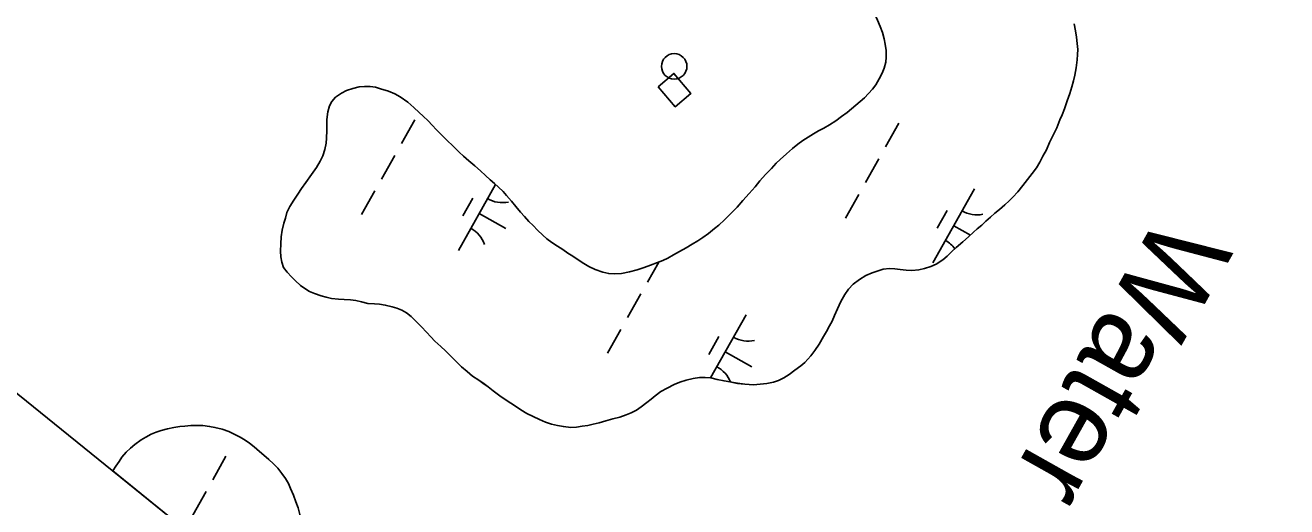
# Model space of a CAD drawing. Extents: x 3913936 to 3933962, y 195330 to 217741.
# Drawn here: x 3922581 to 3923324, y 198286 to 198569 of the extents above; entities that cross this region are included whole.
import ezdxf

# ---------------------------------------------------------------- set-up
doc = ezdxf.new("R2010")
doc.units = 0
for name, color, linetype in [('V-CHAN-DOCK', 7, 'Continuous'), ('V-DOMW-TANK', 7, 'Continuous'), ('V-GRID-FRAM', 7, 'Continuous'), ('V-RIVR-IDEN', 7, 'Continuous'), ('V-TOPO-SHOR', 7, 'Continuous'), ('V-WETL-SWMP', 7, 'Continuous')]:
    doc.layers.add(name, color=color, linetype=linetype)

msp = doc.modelspace()

# ---------------------------------------------------------------- linework, layer by layer
at = {"layer": 'V-CHAN-DOCK'}
msp.add_lwpolyline([(3922953.66, 198532.77), (3922963.71, 198521.05), (3922972.88, 198528.91), (3922962.83, 198540.63)], close=True, dxfattribs=at)
at = {"layer": 'V-DOMW-TANK'}
msp.add_circle((3922963.05, 198544.81), 7.5, dxfattribs=at)
at = {"layer": 'V-GRID-FRAM'}
msp.add_lwpolyline([(3932010.33, 210314.99), (3924440.13, 196848.23), (3917917.56, 202110.57), (3924798.65, 214359.02), (3932010.33, 210314.99)], dxfattribs=at)
at = {"layer": 'V-TOPO-SHOR'}
for points in [[(3923087.39, 198557.97), (3923086.66, 198560.96), (3923085.72, 198564.68), (3923084.47, 198568.29), (3923082.91, 198571.9), (3923081.25, 198575.62), (3923079.69, 198579.23), (3923078.65, 198582.12), (3923072.01, 198591.33)], [(3923198.71, 198569.75), (3923199.45, 198565.72), (3923200.08, 198562), (3923200.5, 198558.29), (3923200.82, 198554.77), (3923200.62, 198551.78), (3923200.53, 198548.58), (3923199.81, 198543.93), (3923199, 198539.58), (3923198.29, 198536.28), (3923197.37, 198532.76), (3923196.04, 198528.83), (3923194.6, 198524.49), (3923192.96, 198519.84), (3923191.52, 198516.22), (3923190.29, 198513.33), (3923188.45, 198508.57), (3923186.4, 198504.33), (3923184.24, 198499.98), (3923182.29, 198495.74), (3923180.23, 198491.91), (3923178.48, 198488.4), (3923176.53, 198485.09), (3923173.96, 198481.67), (3923171.28, 198478.15), (3923168.4, 198474.63), (3923165.42, 198471.01), (3923162.64, 198467.9), (3923160.37, 198465.62), (3923157.9, 198463.24), (3923154.7, 198460.54), (3923152.02, 198458.37), (3923149.34, 198456.09), (3923146.66, 198453.7), (3923144.19, 198451.42), (3923141.62, 198449.15), (3923139.35, 198447.18), (3923136.36, 198444.48), (3923133.06, 198441.58), (3923129.25, 198438.26), (3923126.47, 198435.57), (3923123.79, 198433.08), (3923121.21, 198431.01), (3923117.4, 198428.42), (3923114.2, 198427.07), (3923110.49, 198425.82), (3923107.18, 198425.08), (3923102.95, 198424.66), (3923099.64, 198424.86), (3923096.13, 198425.26), (3923093.03, 198425.66), (3923089.93, 198425.76), (3923086.11, 198425.44), (3923083.22, 198424.5), (3923079.61, 198423.25), (3923076, 198421.69), (3923072.28, 198419.41), (3923068.57, 198416.61), (3923065.79, 198413.71), (3923063.53, 198410.5), (3923061.16, 198406.36), (3923059.32, 198402.02), (3923057.57, 198398.09), (3923056.14, 198394.78), (3923054.59, 198392.19), (3923052.74, 198388.68), (3923051, 198385.78), (3923048.43, 198381.33), (3923045.85, 198377.6), (3923043.48, 198374.4), (3923039.98, 198370.56), (3923037.72, 198368.6), (3923034.21, 198366), (3923030.81, 198363.41), (3923027.72, 198361.44), (3923024.52, 198359.99), (3923021.53, 198359.05), (3923017.6, 198358.21), (3923013.68, 198357.79), (3923009.86, 198357.46), (3923004.59, 198357.76), (3923000.25, 198358.27), (3922995.81, 198359.08), (3922992.4, 198359.69), (3922988.26, 198360.61), (3922984.54, 198361.42), (3922981.23, 198361.72), (3922978.03, 198361.71), (3922974.31, 198361.19), (3922970.19, 198360.14), (3922966.37, 198358.89), (3922963.07, 198357.54), (3922958.84, 198355.46), (3922955.23, 198353.39), (3922951.83, 198350.9), (3922949.46, 198349.03), (3922946.98, 198347.06), (3922943.68, 198344.37)], [(3922790.08, 198531.63), (3922794.63, 198530.3), (3922798.45, 198528.65), (3922801.66, 198526.91), (3922806.21, 198523.72), (3922809.73, 198520.63), (3922812.84, 198517.75), (3922815.22, 198515.48), (3922818.02, 198512.7), (3922820.4, 198510.12), (3922822.99, 198507.45), (3922825.79, 198504.66), (3922828.9, 198501.57), (3922832.94, 198497.55), (3922836.35, 198494.36), (3922838.94, 198491.99), (3922842.15, 198489.22), (3922845.57, 198486.33), (3922848.88, 198483.24), (3922851.89, 198480.57), (3922854.68, 198478.09), (3922857.27, 198475.83), (3922859.55, 198473.67), (3922862.24, 198471.09), (3922864.31, 198468.82), (3922867.22, 198465.53), (3922869.81, 198462.33), (3922872.5, 198459.03), (3922874.78, 198456.46), (3922877.48, 198453.47), (3922879.86, 198451.1), (3922882.55, 198448.42), (3922885.56, 198445.44), (3922888.04, 198443.38), (3922891.04, 198441.21), (3922894.25, 198438.95), (3922897.46, 198437), (3922900.46, 198434.94), (3922903.25, 198433.09), (3922906.98, 198430.62), (3922909.77, 198428.77), (3922912.67, 198427.02), (3922916.4, 198425.27), (3922920.94, 198423.74), (3922924.46, 198422.82), (3922927.76, 198422.62), (3922932, 198422.94), (3922936.64, 198423.89), (3922941.19, 198425.04), (3922945.42, 198426.39), (3922949.13, 198427.74), (3922953.16, 198429.3), (3922956.35, 198430.65), (3922959.24, 198432.01), (3922962.65, 198433.88), (3922966.25, 198435.85), (3922970.07, 198438.03), (3922973.68, 198440.1), (3922976.98, 198442.18), (3922979.87, 198444.15), (3922983.17, 198446.53), (3922986.77, 198449.43), (3922989.25, 198451.4), (3922992.65, 198454.41), (3922995.33, 198457.21), (3922997.9, 198459.8), (3923000.06, 198461.97), (3923003.46, 198465.8), (3923007.27, 198470.05), (3923010.67, 198473.99), (3923013.45, 198477.4), (3923016.75, 198481.23), (3923020.35, 198484.75), (3923023.13, 198487.76), (3923025.5, 198489.93), (3923029.11, 198493.35), (3923032.71, 198496.46), (3923035.81, 198498.95), (3923038.9, 198501.13), (3923041.99, 198503.2), (3923045.08, 198505.17), (3923047.97, 198506.94), (3923051.17, 198508.49), (3923054.57, 198510.47), (3923058.18, 198512.75), (3923061.58, 198515.24), (3923064.88, 198517.73), (3923067.56, 198519.9), (3923070.14, 198521.98), (3923072.51, 198524.05), (3923075.08, 198526.33), (3923077.56, 198528.81), (3923079.82, 198531.3), (3923081.78, 198533.99), (3923083.83, 198537.51), (3923085.48, 198540.71), (3923086.71, 198543.71), (3923087.63, 198547.23), (3923087.93, 198550.23), (3923087.92, 198554.15), (3923087.39, 198557.97)], [(3922943.68, 198344.37), (3922940.8, 198342.5), (3922937.7, 198340.84), (3922934.71, 198339.69), (3922931, 198338.34), (3922926.97, 198337.3), (3922922.84, 198336.15), (3922918.92, 198335.11), (3922915.31, 198334.27), (3922912.1, 198333.54), (3922908.8, 198333.01), (3922905.4, 198332.48), (3922902.19, 198332.37), (3922897.75, 198332.77), (3922894.34, 198333.49), (3922890.72, 198334.3), (3922887.2, 198335.43), (3922883.59, 198336.97), (3922879.86, 198338.71), (3922876.24, 198340.56), (3922872.72, 198342.72), (3922868.9, 198345.19), (3922864.55, 198347.87), (3922860.3, 198350.95), (3922856.47, 198353.94), (3922853.37, 198356.3), (3922850.37, 198358.46), (3922847.89, 198360.21), (3922844.26, 198362.58), (3922841.05, 198365.26), (3922837.74, 198368.04), (3922834.32, 198371.33), (3922831.21, 198374.42), (3922828.31, 198377.31), (3922825.62, 198379.88), (3922822.1, 198383.18), (3922819.61, 198385.65), (3922817.02, 198388.43), (3922814.23, 198391.42), (3922811.12, 198394.72), (3922808.12, 198397.6), (3922805.32, 198399.76), (3922802.63, 198401.3), (3922799.73, 198402.53), (3922796.84, 198403.35), (3922792.81, 198404.27), (3922789.4, 198404.78), (3922786.4, 198404.98), (3922782.58, 198405.28), (3922778.86, 198406.2), (3922775.45, 198407.11), (3922772.35, 198407.42), (3922768.63, 198407.51), (3922765.22, 198407.71), (3922761.19, 198408.21), (3922757.98, 198408.93), (3922755.09, 198409.74), (3922751.06, 198411.18), (3922748.26, 198412.41), (3922745.37, 198414.16), (3922742.88, 198415.91), (3922739.78, 198418.79), (3922737.5, 198420.85), (3922735.01, 198423.63), (3922732.94, 198426.52), (3922731.79, 198429.51), (3922731.27, 198432.71), (3922731.05, 198436.02), (3922731.25, 198440.36), (3922731.44, 198444.39), (3922732.05, 198448.42), (3922733.07, 198452.45), (3922733.99, 198455.45), (3922734.91, 198458.75), (3922736.66, 198462.27), (3922739.03, 198466.1), (3922741.29, 198469.51), (3922743.45, 198472.93), (3922746.12, 198476.55), (3922749.42, 198481.11), (3922752.3, 198485.25), (3922754.56, 198488.97), (3922756, 198492.18), (3922757.23, 198495.8), (3922758.04, 198499.62), (3922758.24, 198502.62), (3922758.43, 198507.16), (3922758.32, 198510.26), (3922758.42, 198513.57), (3922758.92, 198518.11), (3922759.94, 198521.52), (3922761.28, 198524.21), (3922763.54, 198526.6), (3922766.95, 198529.08), (3922769.94, 198530.54), (3922773.65, 198531.79), (3922777.37, 198532.73), (3922780.67, 198533.05), (3922783.88, 198532.95), (3922787.08, 198532.55), (3922790.08, 198531.63)], [(3922632.39, 198306.69), (3922634, 198309.5), (3922635.97, 198312.32), (3922637.64, 198314.83), (3922640.13, 198317.76), (3922642.73, 198320.17), (3922645.34, 198322.36), (3922648.98, 198324.99), (3922651.69, 198326.56), (3922654.92, 198328.34), (3922657.84, 198329.5), (3922660.76, 198330.44), (3922664.62, 198331.5), (3922668.27, 198332.24), (3922671.71, 198332.77), (3922674.73, 198333.09), (3922678.18, 198333.52), (3922681.2, 198333.53), (3922685.27, 198333.43), (3922689.34, 198332.92), (3922692.47, 198332.31), (3922696.75, 198331.38), (3922700.62, 198329.93), (3922703.44, 198328.58), (3922707.41, 198326.5), (3922710.23, 198324.74), (3922712.74, 198323.08), (3922715.57, 198320.89), (3922718.81, 198318.19), (3922721.32, 198316), (3922724.25, 198313.4), (3922726.97, 198310.8), (3922729.48, 198308.3), (3922731.89, 198305.29), (3922733.98, 198302.26), (3922735.77, 198299.35), (3922737.03, 198296.43), (3922738.81, 198292.37), (3922740.18, 198288.61)], [(3922740.18, 198288.61), (3922741.44, 198284.96), (3922742.39, 198281.83), (3922743.02, 198278.71), (3922743.66, 198275.58), (3922743.98, 198272.45), (3922744.2, 198269.42), (3922744.21, 198264.52), (3922743.8, 198260.87), (3922743.4, 198257.73), (3922742.99, 198254.71), (3922742.37, 198250.22), (3922741.76, 198246.25), (3922741.25, 198242.18), (3922740.95, 198239.05), (3922740.44, 198233.73), (3922740.24, 198228.72), (3922740.04, 198225.17), (3922739.6, 198220.19)]]:
    msp.add_lwpolyline(points, dxfattribs=at)
at = {"layer": 'V-WETL-SWMP'}
for p, q in [((3922810.2, 198513.32), (3922802.36, 198499.38)), ((3923095.4, 198511.32), (3923087.56, 198497.37)), ((3922798.44, 198492.4), (3922790.6, 198478.46)), ((3923083.64, 198490.4), (3923075.79, 198476.45)), ((3922786.68, 198471.48), (3922778.84, 198457.54)), ((3922857.74, 198475.38), (3922835.87, 198436.47)), ((3923139.97, 198472.83), (3923115.47, 198429.25)), ((3922844.33, 198467.27), (3922838.45, 198456.81)), ((3923071.87, 198469.47), (3923064.03, 198455.53)), ((3922848.12, 198458.26), (3922863.81, 198449.44)), ((3923123.94, 198460.05), (3923118.06, 198449.59)), ((3923127.72, 198451.04), (3923137.52, 198445.53)), ((3922953.99, 198429.65), (3922947.36, 198417.87)), ((3922943.44, 198410.89), (3922935.6, 198396.95)), ((3923005.37, 198398.54), (3922984.5, 198361.43)), ((3922931.68, 198389.97), (3922923.84, 198376.03)), ((3922989.33, 198385.76), (3922983.45, 198375.3)), ((3922993.12, 198376.75), (3923008.81, 198367.93)), ((3922657.84, 198329.5), (3922654.92, 198328.34)), ((3922660.76, 198330.44), (3922657.84, 198329.5)), ((3922664.62, 198331.5), (3922660.76, 198330.44)), ((3922668.27, 198332.24), (3922664.62, 198331.5)), ((3922671.71, 198332.77), (3922668.27, 198332.24)), ((3922674.73, 198333.09), (3922671.71, 198332.77)), ((3922678.18, 198333.52), (3922674.73, 198333.09)), ((3922681.2, 198333.53), (3922678.18, 198333.52)), ((3922685.27, 198333.43), (3922681.2, 198333.53)), ((3922689.34, 198332.92), (3922685.27, 198333.43)), ((3922692.48, 198332.31), (3922689.34, 198332.92)), ((3922696.75, 198331.38), (3922692.48, 198332.31)), ((3922700.62, 198329.93), (3922696.75, 198331.38)), ((3922703.44, 198328.58), (3922700.62, 198329.93)), ((3922645.34, 198322.36), (3922642.73, 198320.17)), ((3922648.98, 198324.98), (3922645.34, 198322.36)), ((3922651.69, 198326.56), (3922648.98, 198324.98)), ((3922654.92, 198328.34), (3922651.69, 198326.56)), ((3922707.41, 198326.5), (3922703.44, 198328.58)), ((3922710.23, 198324.74), (3922707.41, 198326.5)), ((3922712.74, 198323.08), (3922710.23, 198324.74)), ((3922715.57, 198320.89), (3922712.74, 198323.08)), ((3922637.64, 198314.83), (3922635.97, 198312.32)), ((3922640.13, 198317.76), (3922637.64, 198314.83)), ((3922642.73, 198320.17), (3922640.13, 198317.76)), ((3922698.99, 198315.49), (3922691.15, 198301.54)), ((3922718.81, 198318.19), (3922715.57, 198320.89)), ((3922721.32, 198316), (3922718.81, 198318.19)), ((3922724.25, 198313.4), (3922721.32, 198316)), ((3922634, 198309.5), (3922632.39, 198306.69)), ((3922632.39, 198306.69), (3922739.6, 198220.2)), ((3922635.97, 198312.32), (3922634, 198309.5)), ((3922726.97, 198310.8), (3922724.25, 198313.4)), ((3922729.48, 198308.3), (3922726.97, 198310.8)), ((3922731.89, 198305.29), (3922729.48, 198308.3)), ((3922733.98, 198302.27), (3922731.89, 198305.29)), ((3922735.77, 198299.35), (3922733.98, 198302.27)), ((3922737.03, 198296.43), (3922735.77, 198299.35)), ((3922687.23, 198294.57), (3922679.39, 198280.62)), ((3922738.81, 198292.36), (3922737.03, 198296.43)), ((3922740.18, 198288.61), (3922738.81, 198292.36)), ((3922741.44, 198284.96), (3922740.18, 198288.61))]:
    msp.add_line(p, q, dxfattribs=at)
for points in [[(3923198.71, 198569.75), (3923199.45, 198565.72), (3923200.08, 198562), (3923200.5, 198558.29), (3923200.82, 198554.77), (3923200.62, 198551.78), (3923200.53, 198548.58), (3923199.82, 198543.93), (3923199, 198539.58), (3923198.29, 198536.28), (3923197.37, 198532.76), (3923196.04, 198528.83), (3923194.6, 198524.49), (3923192.96, 198519.84), (3923191.53, 198516.22), (3923190.29, 198513.32), (3923188.45, 198508.57), (3923186.4, 198504.33), (3923184.24, 198499.98), (3923182.29, 198495.74), (3923180.23, 198491.91), (3923178.48, 198488.4), (3923176.53, 198485.09), (3923173.96, 198481.67), (3923171.28, 198478.15), (3923168.4, 198474.63), (3923165.42, 198471.01), (3923162.64, 198467.9), (3923160.37, 198465.62), (3923157.9, 198463.24), (3923154.7, 198460.54), (3923152.02, 198458.37), (3923149.34, 198456.09), (3923146.66, 198453.7), (3923144.19, 198451.42), (3923141.62, 198449.15), (3923139.35, 198447.18), (3923136.36, 198444.48), (3923133.06, 198441.58), (3923129.25, 198438.26), (3923126.47, 198435.57), (3923123.79, 198433.08), (3923121.21, 198431.01), (3923117.4, 198428.42), (3923114.2, 198427.07), (3923110.48, 198425.82), (3923107.18, 198425.08), (3923102.95, 198424.66), (3923099.64, 198424.86), (3923096.13, 198425.26), (3923093.03, 198425.67), (3923089.93, 198425.76), (3923086.11, 198425.44), (3923083.22, 198424.5), (3923079.61, 198423.25), (3923076, 198421.69), (3923072.28, 198419.41), (3923068.57, 198416.61), (3923065.79, 198413.71), (3923063.53, 198410.5), (3923061.16, 198406.36), (3923059.32, 198402.02), (3923057.57, 198398.09), (3923056.14, 198394.78), (3923054.59, 198392.19), (3923052.74, 198388.68), (3923051, 198385.78), (3923048.43, 198381.33), (3923045.85, 198377.6), (3923043.49, 198374.4), (3923039.98, 198370.56), (3923037.72, 198368.59), (3923034.21, 198366), (3923030.81, 198363.41), (3923027.72, 198361.44), (3923024.52, 198359.98), (3923021.53, 198359.05), (3923017.6, 198358.21), (3923013.68, 198357.79), (3923009.86, 198357.46), (3923004.59, 198357.76), (3923000.25, 198358.26), (3922995.81, 198359.08), (3922992.4, 198359.69), (3922988.26, 198360.61), (3922984.54, 198361.42), (3922981.23, 198361.72), (3922978.03, 198361.71), (3922974.31, 198361.19), (3922970.19, 198360.14)], [(3923087.39, 198557.97), (3923086.66, 198560.96), (3923085.72, 198564.68), (3923084.47, 198568.29), (3923082.91, 198571.9)], [(3922790.08, 198531.63), (3922794.63, 198530.3), (3922798.45, 198528.65), (3922801.66, 198526.91), (3922806.21, 198523.72), (3922809.73, 198520.63), (3922812.84, 198517.75), (3922815.22, 198515.48), (3922818.02, 198512.7), (3922820.4, 198510.12), (3922822.99, 198507.45), (3922825.79, 198504.66), (3922828.9, 198501.57), (3922832.94, 198497.56), (3922836.35, 198494.36), (3922838.94, 198491.99), (3922842.15, 198489.21), (3922845.57, 198486.33), (3922848.88, 198483.24), (3922851.89, 198480.57), (3922854.68, 198478.09), (3922857.27, 198475.83), (3922859.55, 198473.67), (3922862.24, 198471.09), (3922864.31, 198468.82), (3922867.22, 198465.53), (3922869.81, 198462.33), (3922872.5, 198459.03), (3922874.78, 198456.46), (3922877.48, 198453.47), (3922879.86, 198451.1), (3922882.55, 198448.42), (3922885.56, 198445.43), (3922888.04, 198443.38), (3922891.04, 198441.21), (3922894.25, 198438.95), (3922897.46, 198437), (3922900.46, 198434.94), (3922903.25, 198433.09), (3922906.98, 198430.62), (3922909.77, 198428.77), (3922912.67, 198427.02), (3922916.39, 198425.27), (3922920.94, 198423.74), (3922924.46, 198422.82), (3922927.76, 198422.62), (3922932, 198422.94), (3922936.64, 198423.89), (3922941.19, 198425.04), (3922945.42, 198426.39), (3922949.13, 198427.74), (3922953.16, 198429.3), (3922956.35, 198430.65), (3922959.24, 198432.01), (3922962.65, 198433.88), (3922966.26, 198435.85), (3922970.07, 198438.03), (3922973.68, 198440.1), (3922976.98, 198442.18), (3922979.87, 198444.15), (3922983.17, 198446.53), (3922986.77, 198449.44), (3922989.25, 198451.41), (3922992.65, 198454.41), (3922995.33, 198457.21), (3922997.9, 198459.8), (3923000.06, 198461.97), (3923003.46, 198465.8), (3923007.27, 198470.05), (3923010.67, 198473.98), (3923013.45, 198477.4), (3923016.75, 198481.23), (3923020.35, 198484.75), (3923023.13, 198487.76), (3923025.5, 198489.93), (3923029.11, 198493.35), (3923032.71, 198496.46), (3923035.81, 198498.95), (3923038.9, 198501.13), (3923041.99, 198503.2), (3923045.08, 198505.17), (3923047.97, 198506.94), (3923051.17, 198508.49), (3923054.57, 198510.47), (3923058.18, 198512.75), (3923061.58, 198515.24), (3923064.88, 198517.73), (3923067.56, 198519.9), (3923070.14, 198521.98), (3923072.51, 198524.05), (3923075.08, 198526.33), (3923077.56, 198528.81), (3923079.82, 198531.3), (3923081.78, 198533.99), (3923083.83, 198537.51), (3923085.48, 198540.71), (3923086.71, 198543.71), (3923087.63, 198547.23), (3923087.93, 198550.23), (3923087.92, 198554.15), (3923087.39, 198557.97)], [(3922763.54, 198526.6), (3922766.95, 198529.08), (3922769.94, 198530.54), (3922773.65, 198531.79), (3922777.37, 198532.73), (3922780.67, 198533.05), (3922783.88, 198532.95), (3922787.08, 198532.55), (3922790.08, 198531.63)], [(3922970.19, 198360.14), (3922966.37, 198358.89), (3922963.07, 198357.54), (3922958.84, 198355.46), (3922955.23, 198353.39), (3922951.83, 198350.9), (3922949.46, 198349.03), (3922946.98, 198347.06), (3922943.68, 198344.37), (3922940.8, 198342.5), (3922937.7, 198340.84), (3922934.71, 198339.69), (3922931, 198338.34), (3922926.97, 198337.3), (3922922.84, 198336.15), (3922918.92, 198335.11), (3922915.31, 198334.27), (3922912.1, 198333.54), (3922908.8, 198333.01), (3922905.39, 198332.49), (3922902.19, 198332.37), (3922897.75, 198332.77), (3922894.34, 198333.49), (3922890.72, 198334.3), (3922887.21, 198335.43), (3922883.59, 198336.97), (3922879.86, 198338.71), (3922876.24, 198340.56), (3922872.72, 198342.72), (3922868.9, 198345.19), (3922864.55, 198347.87), (3922860.31, 198350.95), (3922856.48, 198353.94), (3922853.37, 198356.3), (3922850.37, 198358.47), (3922847.88, 198360.21), (3922844.26, 198362.58), (3922841.05, 198365.26), (3922837.74, 198368.04), (3922834.32, 198371.33), (3922831.21, 198374.42), (3922828.31, 198377.31), (3922825.62, 198379.88), (3922822.1, 198383.18), (3922819.61, 198385.65), (3922817.02, 198388.43), (3922814.23, 198391.42), (3922811.12, 198394.72), (3922808.11, 198397.6), (3922805.32, 198399.76), (3922802.63, 198401.3), (3922799.73, 198402.54), (3922796.84, 198403.35), (3922792.81, 198404.27), (3922789.4, 198404.78), (3922786.4, 198404.98), (3922782.58, 198405.28), (3922778.86, 198406.2), (3922775.45, 198407.11), (3922772.35, 198407.42), (3922768.63, 198407.51), (3922765.22, 198407.71), (3922761.19, 198408.21), (3922757.98, 198408.93), (3922755.09, 198409.74), (3922751.06, 198411.18), (3922748.27, 198412.41), (3922745.37, 198414.16), (3922742.88, 198415.91), (3922739.78, 198418.79), (3922737.5, 198420.85), (3922735.01, 198423.63), (3922732.94, 198426.52), (3922731.79, 198429.51), (3922731.27, 198432.71), (3922731.05, 198436.02), (3922731.25, 198440.36), (3922731.44, 198444.39), (3922732.05, 198448.42), (3922733.07, 198452.45), (3922733.99, 198455.45), (3922734.91, 198458.75), (3922736.66, 198462.27), (3922739.02, 198466.1), (3922741.29, 198469.51), (3922743.45, 198472.93), (3922746.12, 198476.55), (3922749.42, 198481.11), (3922752.3, 198485.25), (3922754.56, 198488.97), (3922756, 198492.18), (3922757.23, 198495.8), (3922758.04, 198499.62), (3922758.24, 198502.62), (3922758.43, 198507.16), (3922758.32, 198510.26), (3922758.42, 198513.57), (3922758.92, 198518.11), (3922759.94, 198521.52), (3922761.28, 198524.21), (3922763.54, 198526.6)]]:
    msp.add_lwpolyline(points, dxfattribs=at)
for centre, start, end in [((3922861.86, 198482.22), 239.88608, 281.42974), ((3923141.46, 198475), 239.88608, 281.42974), ((3922834.79, 198434.06), 19.88608, 61.42973), ((3923114.39, 198426.85), 37.13106, 61.42973), ((3923006.86, 198400.71), 239.88608, 281.42974), ((3922979.79, 198352.56), 21.47815, 61.42973)]:
    msp.add_arc(centre, 17.62, start, end, dxfattribs=at)

# ---------------------------------------------------------------- texts
at = {"layer": 'V-RIVR-IDEN'}
msp.add_text('Water', height=50, rotation=240.67305, dxfattribs=at).set_placement((3923249.04, 198459.64))

doc.saveas('drawing.dxf')
